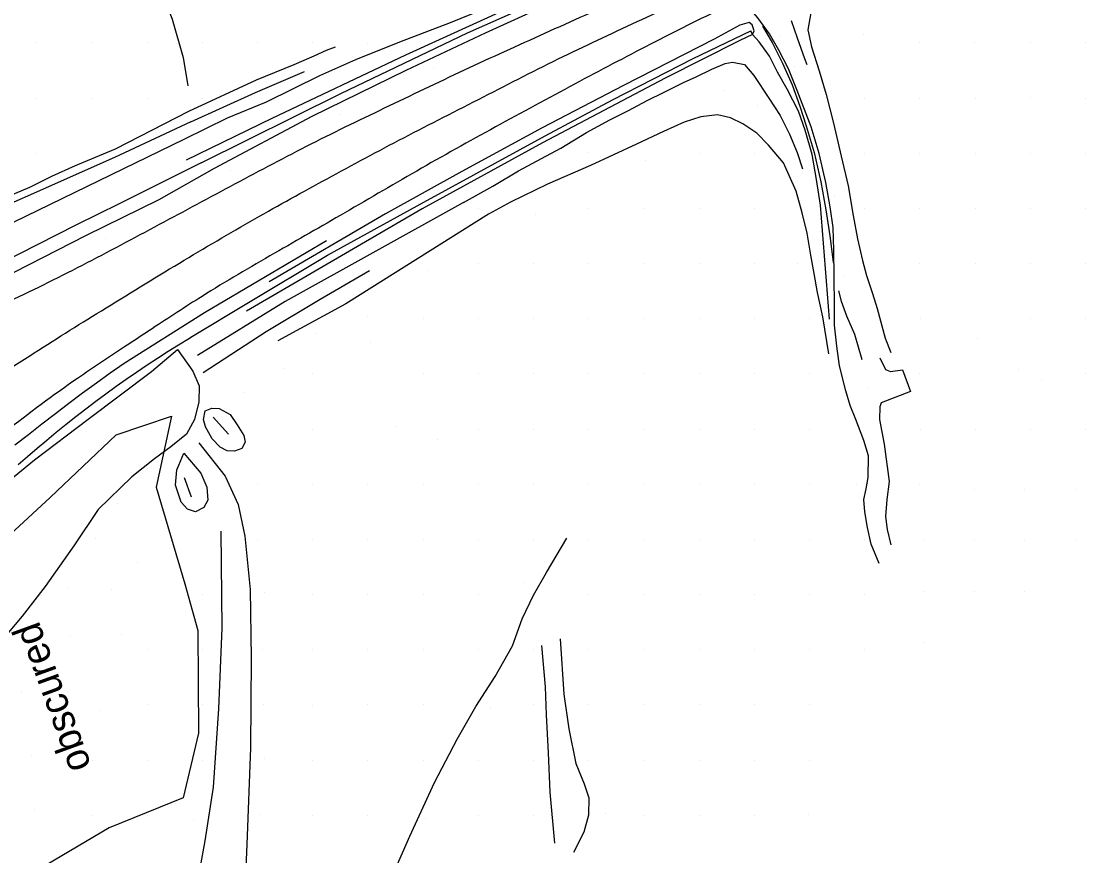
# Model space of a CAD drawing. Extents: x 524772 to 528246, y 273285 to 283088.
# Drawn here: x 527033.7 to 527223, y 277405.3 to 277552.7 of the extents above; entities that cross this region are included whole.
import ezdxf

# ---------------------------------------------------------------- set-up
doc = ezdxf.new("R2010")
doc.units = 0
for name, color, linetype in [('Exist DTM Crownline', 7, 'Continuous'), ('Exist DTM Spot Elevation CELL', 7, 'Continuous'), ('Exist Roads EOP', 7, 'Continuous'), ('Old_Level_12', 7, 'Continuous'), ('PH Exist DTM Breakline', 7, 'Continuous'), ('PH Exist DTM Obscure Area', 7, 'Continuous'), ('PH Exist DTM Point', 7, 'Continuous')]:
    doc.layers.add(name, color=color, linetype=linetype)

msp = doc.modelspace()

# ---------------------------------------------------------------- linework, layer by layer
at = {"layer": 'Exist DTM Crownline'}
msp.add_spline([(527012.9, 277479), (527035.13, 277493.63), (527047.79, 277501.59), (527061.59, 277510.01), (527074.93, 277517.83), (527087.69, 277524.92), (527101.22, 277532.16), (527115.31, 277539.39), (527129.4, 277546.52), (527143.33, 277553.09), (527157.2, 277559.38), (527172, 277565.61), (527185.97, 277571.18), (527200.44, 277576.75), (527213.91, 277581.57), (527228.29, 277586.39), (527242.7, 277590.91), (527257.14, 277595.19), (527271.79, 277599.28)], degree=3, dxfattribs=at)
at = {"layer": 'Exist DTM Spot Elevation CELL'}
msp.add_line((527045.97, 277474.93), (527045.97, 277474.93), dxfattribs=at)
at = {"layer": 'Exist Roads EOP'}
for points in [[(527270.78, 277603.37), (527256.06, 277599.09), (527241.65, 277594.75), (527227.06, 277590.17), (527212.47, 277585.21), (527198.44, 277580.12), (527184.35, 277574.63), (527170.36, 277569.05), (527155.19, 277563.06), (527141.3, 277557.34), (527127, 277550.99), (527112.8, 277544.51), (527098.63, 277537.78), (527084.82, 277531.02), (527071.32, 277523.94), (527058.01, 277516.8), (527044.38, 277509.59), (527030.61, 277502.78), (527016.27, 277496.31), (527001.86, 277490.41), (526987.67, 277485.12)], [(527272.57, 277596.68), (527258.04, 277592.42), (527243.99, 277587.67), (527229.51, 277583.19), (527215.42, 277578.37), (527201.07, 277573.4), (527187.28, 277567.87), (527173.13, 277562.03), (527158.7, 277555.6), (527145.65, 277549.11), (527132.3, 277542.12), (527118.3, 277534.55), (527104.37, 277526.77), (527090.79, 277518.88), (527078.39, 277511.74), (527065.58, 277504.12), (527056.77, 277498.41), (527052.06, 277495.3), (527043.57, 277489.61), (527030.84, 277480.16), (527019.08, 277470.24), (527008.57, 277460.31), (526997.6, 277449.4)]]:
    msp.add_spline(points, degree=3, dxfattribs=at)
at = {"layer": 'Old_Level_12'}
msp.add_lwpolyline([(526985.25, 277411.31), (526998.8, 277426.7), (527015.52, 277447.03), (527028.53, 277459.17), (527038.72, 277468.55), (527050.4, 277479.65), (527060.21, 277482.96), (527057.46, 277470.38), (527062.53, 277453.28), (527064.85, 277445.08), (527064.96, 277426.88), (527062.27, 277415.48), (527049.18, 277410.15), (527037.93, 277403.49), (527029.44, 277395.78), (527025.35, 277392.96), (527024.45, 277389.54), (527021.62, 277387.08), (527013.37, 277383.47), (527005.76, 277383.08), (526993.31, 277388.45), (526984.9, 277407.03)], dxfattribs=at)
at = {"layer": 'PH Exist DTM Breakline'}
for points in [[(527029.64, 277607.72), (527033.91, 277601.98), (527037.04, 277598.47), (527040.59, 277593.93), (527044.34, 277589.32), (527048.32, 277584.35), (527052.04, 277577.84), (527053.61, 277571.61), (527057.13, 277561.42), (527060.31, 277553.12), (527062.23, 277546.37), (527063.09, 277541.35)], [(527067.81, 277526.76), (527085.06, 277535.97), (527101.63, 277544.09), (527115.66, 277550.72), (527133.31, 277558.81), (527133.9, 277559.09), (527134.17, 277559.51), (527133.43, 277561.02), (527131.86, 277560.35), (527120.05, 277555.21), (527101.51, 277546.74), (527077.94, 277535.54), (527062.77, 277528.22)], [(527065.43, 277527.74), (527090.09, 277539.96), (527112.47, 277550.7), (527133.4, 277560.02)], [(527121.35, 277557.37), (527109.43, 277552.48), (527100.46, 277549.04), (527092.7, 277545.92), (527086.35, 277543.09), (527076.94, 277538.45), (527070.01, 277535.63), (527062.35, 277531.86)], [(527178.21, 277491.85), (527177.74, 277495.31), (527177.36, 277499.01), (527177.34, 277502.43), (527177.28, 277507.62), (527177.22, 277512.26), (527177.09, 277516.29), (527176.57, 277519.94), (527175.8, 277524.23), (527174.63, 277529.4), (527173.2, 277534.12), (527170.76, 277540.53), (527169.2, 277544.36), (527167.51, 277547.62), (527165.87, 277550.51), (527163.78, 277553.37), (527162.68, 277554.66), (527157.8, 277554.15), (527156.97, 277554.25)], [(527173.18, 277554.23), (527172.64, 277551.24), (527173.26, 277548.24), (527174.65, 277543.97), (527175.89, 277539.82), (527177.16, 277534.77), (527178.54, 277528.92), (527179.75, 277523.64), (527180.66, 277518.39), (527181.4, 277514.32), (527182.29, 277510.48), (527183.03, 277507.83), (527184.05, 277504.62), (527184.86, 277501.97), (527186.32, 277496.73), (527187.28, 277494.19)], [(527162.83, 277550.39), (527163.17, 277551.07), (527162.81, 277552.11), (527162.26, 277552.55), (527160.59, 277552.04), (527156.08, 277549.59), (527140.08, 277541.4), (527125.7, 277533.89), (527111.49, 277526.19), (527098.02, 277518.73), (527077.46, 277506.69)], [(527169.71, 277552.91), (527170.76, 277549.84), (527172.03, 277546.16), (527172.45, 277545.12)], [(527162.83, 277550.39), (527160.63, 277549.34), (527147.45, 277542.69), (527125.77, 277531.27), (527104.49, 277519.57), (527073.45, 277501.53)], [(527087.77, 277511.38), (527104.8, 277520.78), (527126.19, 277532.48), (527138.12, 277538.86), (527152.38, 277546.19), (527162.55, 277551.04)], [(527176.49, 277500.12), (527174.85, 277520.24), (527174.18, 277524.79), (527173.43, 277529.18), (527172.17, 277533.52), (527170.96, 277536.87), (527169, 277540.77), (527167.3, 277543.78), (527165.86, 277546.59), (527164.03, 277549.11), (527162.83, 277550.39), (527162.55, 277551.04)], [(527164.6, 277551.91), (527166.31, 277549.03), (527168.14, 277545.33), (527169.86, 277541.49), (527171.2, 277537.75), (527172.32, 277534.24), (527173.77, 277529.53), (527174.96, 277524.38), (527175.84, 277519.42), (527176.51, 277514.83), (527177.14, 277510.19), (527177.15, 277510.11)], [(527063.24, 277536.84), (527075.18, 277542.38), (527081.88, 277545.14), (527085.39, 277546.64), (527087.58, 277547.63), (527089.14, 277548.26)], [(527111.78, 277520.69), (527116.96, 277523.62), (527121.5, 277526.31), (527125.57, 277528.5), (527129, 277530.34), (527133.55, 277533.08), (527137.64, 277535.31), (527140.92, 277536.98), (527144.23, 277538.73), (527147.24, 277540.23), (527150.68, 277541.93), (527152.89, 277542.96), (527155.67, 277544.3), (527158, 277545.27), (527159.34, 277545.52), (527161.44, 277545.12), (527163.12, 277543.19), (527165.73, 277539.15), (527167.72, 277536.12), (527169.37, 277532.8), (527170.76, 277529.58), (527171.71, 277526.64)], [(527063.63, 277534.95), (527075.01, 277540.14), (527083.71, 277543.88)], [(527025.7, 277519.5), (527035.15, 277523.43), (527039.04, 277525.37), (527043.24, 277527.24), (527050.32, 277530.19), (527063.24, 277536.84)], [(527176.35, 277493.99), (527175.31, 277500.52), (527174.36, 277504.82), (527173.73, 277508.17), (527173.18, 277511.41), (527172.5, 277515.3), (527171.62, 277518.88), (527170.56, 277522.74), (527168.34, 277527.71), (527165.69, 277530.88), (527163.61, 277532.96), (527161.17, 277534.6), (527158.99, 277535.71), (527156.65, 277536.21), (527153.73, 277535.87), (527150.78, 277534.93), (527147.14, 277533.27), (527142.37, 277531.03), (527134.21, 277527.24), (527126.62, 277523.93), (527120.1, 277520.75), (527116.19, 277518.64), (527091, 277502.82), (527078.95, 277496.25)], [(527063.63, 277534.95), (527050.12, 277528.7), (527017.93, 277514.39), (527007.64, 277509.27), (526958.35, 277490.57), (526947.83, 277487.25), (526930.21, 277481.91), (526921.71, 277479.07), (526911.59, 277476.32), (526905.56, 277474.55), (526894.03, 277470.8), (526881.77, 277466.68), (526874.81, 277464.71)], [(527062.35, 277531.86), (527019.31, 277510.96), (527008.52, 277506.7), (526971.15, 277490.83), (526956.27, 277485.74), (526924.85, 277476.2), (526912.85, 277473.02), (526901.93, 277470.15), (526894.22, 277467.82), (526885.23, 277465), (526878.81, 277463.4), (526872.26, 277462.31), (526866.92, 277461.65), (526860.41, 277460.41)], [(527065.43, 277527.74), (527050.92, 277520.46), (527043.26, 277516.7), (527023.06, 277506.47)], [(527032.37, 277508.41), (527045.18, 277514.92), (527057.98, 277521.25), (527067.81, 277526.76)], [(527111.78, 277520.69), (527080.26, 277503.19), (527064.79, 277493.64)], [(527087.57, 277513.93), (527066, 277501.19), (527051.83, 277492.27), (527049.37, 277490.53), (527046.92, 277488.77), (527044.48, 277486.99), (527042.06, 277485.19), (527039.66, 277483.37), (527037.27, 277481.53), (527034.89, 277479.67), (527032.53, 277477.79)], [(527033.1, 277474.37), (527034.76, 277475.84), (527036.44, 277477.29), (527038.13, 277478.72), (527039.83, 277480.14), (527041.56, 277481.53), (527043.29, 277482.91), (527045.04, 277484.26), (527046.81, 277485.6), (527048.59, 277486.92), (527050.39, 277488.22), (527052.2, 277489.5), (527054.02, 277490.75), (527055.86, 277491.99), (527057.71, 277493.21), (527059.58, 277494.41), (527061.45, 277495.58), (527063.34, 277496.74), (527063.63, 277496.91), (527073.8, 277503.05), (527087.77, 277511.38)], [(527065.77, 277490.65), (527076.94, 277497.89), (527086.45, 277503.64), (527095.15, 277508.67)], [(527178.08, 277505.12), (527178.5, 277503.28), (527179.48, 277500.7), (527180.9, 277497.42), (527182.18, 277492.98)], [(527185.23, 277456.89), (527183.85, 277460.31), (527183.17, 277463.25), (527182.71, 277466.06), (527182.56, 277468.23), (527182.96, 277470.12), (527183.32, 277472.09), (527183.37, 277475.94), (527182.55, 277478.64), (527181.14, 277482.36), (527180.14, 277484.8), (527179.36, 277487.41), (527178.21, 277491.85)], [(527185.33, 277493.28), (527186.34, 277491.21), (527187.27, 277490.82), (527189.37, 277491.13), (527190.77, 277487.32), (527185.62, 277485.3), (527185.33, 277484.61), (527185.31, 277482.37), (527186.13, 277477.99), (527187, 277471.38), (527186.62, 277468.21), (527186.37, 277465.2), (527186.65, 277462.93), (527187.29, 277460.21)], [(527067.35, 277478.94), (527066.17, 277481.07), (527065.84, 277482.38), (527066.12, 277483.89), (527067.31, 277484.38), (527068.64, 277484.28), (527070.57, 277483.25), (527071.77, 277481.44), (527072.96, 277479.51), (527073.19, 277478.33), (527072.62, 277477.2), (527071.32, 277476.73), (527070.04, 277476.83), (527068.77, 277477.44), (527067.35, 277478.94)], [(527067.56, 277482.76), (527070.24, 277479.79)], [(527065, 277478.23), (527069.7, 277472.34), (527071.99, 277467.32), (527073.16, 277461.72), (527074.06, 277452.3), (527074.26, 277440.14), (527074.17, 277424.31), (527073.51, 277407.25), (527072.93, 277393.76), (527072.77, 277383.09), (527074.19, 277377.88), (527076.18, 277374.75), (527077.89, 277373.26), (527082.45, 277372.14), (527089.59, 277370.85), (527105.79, 277369.94), (527118.86, 277369.65), (527129.85, 277368.57), (527134.5, 277367.52), (527136.83, 277366.1), (527140.6, 277362.79), (527143.4, 277358.9), (527146.2, 277353.21)], [(527062.36, 277476.42), (527065.38, 277472.85), (527066.46, 277470.39), (527066.58, 277468.07), (527065.88, 277466.79), (527064.42, 277466.06), (527062.99, 277466.5), (527061.91, 277467.74), (527060.91, 277470.76), (527061.15, 277473.46), (527061.5, 277474.27), (527062.36, 277476.42)], [(527062.45, 277472.12), (527063.68, 277468.67)], [(527068.93, 277462.64), (527069.08, 277445.49), (527068.51, 277431.2), (527067.54, 277417.37), (527066.08, 277407.89), (527064.58, 277399.74), (527064.32, 277392.42), (527064.9, 277386.93), (527066.11, 277380.8), (527068.58, 277375.41), (527069.7, 277374.19)], [(527098.03, 277398.89), (527102.32, 277408.67), (527106.69, 277418.16), (527110.65, 277425.84), (527113.96, 277431.62), (527117.4, 277436.9), (527120.43, 277442.33), (527122.13, 277447.11), (527124.14, 277451.28), (527126.45, 277455.31), (527130.04, 277461.4)], [(527127.93, 277407.46), (527127.08, 277416.47), (527126.82, 277423.4), (527126.48, 277430.12), (527126.28, 277435.1), (527125.64, 277442.41)], [(527128.89, 277443.57), (527129.51, 277433.8), (527130.43, 277427.65), (527131.64, 277421.53), (527133.13, 277417.92), (527133.92, 277415.45), (527133.88, 277412.41), (527133.07, 277409.39), (527131.23, 277405.8)]]:
    msp.add_lwpolyline(points, dxfattribs=at)
at = {"layer": 'PH Exist DTM Obscure Area'}
for points in [[(527022.51, 277464.18), (527035.99, 277475.25), (527045.49, 277482.44), (527056.63, 277490.85), (527061.25, 277494.75)], [(527061.25, 277494.75), (527063.97, 277490.91), (527065.06, 277488.31), (527065.02, 277485.47), (527064.25, 277482.33), (527062.84, 277479.78), (527060.07, 277477.5), (527057.17, 277475.39), (527053.15, 277472.24), (527047.25, 277466.43), (527042.95, 277460.01), (527037.86, 277452.84), (527033.79, 277447.59), (527030.39, 277443.54)]]:
    msp.add_lwpolyline(points, dxfattribs=at)
at = {"layer": 'PH Exist DTM Point'}
for p, q in [((527182.52, 277550.47), (527182.52, 277550.47)), ((527036.39, 277548.93), (527036.39, 277548.93)), ((527046.14, 277548.93), (527046.14, 277548.93)), ((527055.9, 277548.93), (527055.9, 277548.93)), ((527065.63, 277548.92), (527065.63, 277548.92)), ((527075.4, 277548.93), (527075.4, 277548.93)), ((527085.16, 277548.93), (527085.16, 277548.93)), ((527094.91, 277548.9), (527094.91, 277548.9)), ((527167.6, 277550.15), (527167.6, 277550.15)), ((527192.45, 277548.93), (527192.45, 277548.93)), ((527202.17, 277548.98), (527202.17, 277548.98)), ((527211.96, 277548.93), (527211.96, 277548.93)), ((527221.68, 277548.94), (527221.68, 277548.94)), ((527170.32, 277544.82), (527170.32, 277544.82)), ((527106.48, 277544.49), (527106.48, 277544.49)), ((527036.39, 277539.18), (527036.39, 277539.18)), ((527046.14, 277539.18), (527046.14, 277539.18)), ((527055.9, 277539.18), (527055.9, 277539.18)), ((527065.65, 277539.18), (527065.65, 277539.18)), ((527157.93, 277540.49), (527157.93, 277540.49)), ((527182.69, 277539.18), (527182.69, 277539.18)), ((527192.45, 277539.18), (527192.45, 277539.18)), ((527202.2, 277539.18), (527202.2, 277539.18)), ((527211.95, 277539.22), (527211.95, 277539.22)), ((527221.71, 277539.18), (527221.71, 277539.18)), ((527163.67, 277537.89), (527163.67, 277537.89)), ((527089.98, 277536.3), (527089.98, 277536.3)), ((527174.26, 277534.57), (527174.26, 277534.57)), ((527133.84, 277529.64), (527133.84, 277529.64)), ((527036.39, 277529.42), (527036.39, 277529.42)), ((527144.03, 277528.14), (527144.03, 277528.14)), ((527153.43, 277529.42), (527153.43, 277529.42)), ((527163.19, 277529.42), (527163.19, 277529.42)), ((527182.69, 277529.42), (527182.69, 277529.42)), ((527192.45, 277529.42), (527192.45, 277529.42)), ((527202.2, 277529.42), (527202.2, 277529.42)), ((527211.97, 277529.41), (527211.97, 277529.41)), ((527221.71, 277529.42), (527221.71, 277529.42)), ((527070.65, 277526.3), (527070.65, 277526.3)), ((527177.39, 277521.82), (527177.39, 277521.82)), ((527114.42, 277519.67), (527114.42, 277519.67)), ((527124.51, 277518.65), (527124.51, 277518.65)), ((527133.93, 277519.67), (527133.93, 277519.67)), ((527143.68, 277519.64), (527143.68, 277519.64)), ((527153.43, 277519.67), (527153.43, 277519.67)), ((527163.19, 277519.67), (527163.19, 277519.67)), ((527182.69, 277519.67), (527182.69, 277519.67)), ((527192.45, 277519.67), (527192.45, 277519.67)), ((527202.2, 277519.67), (527202.2, 277519.67)), ((527212.01, 277519.59), (527212.01, 277519.59)), ((527221.72, 277519.65), (527221.72, 277519.65)), ((527048.55, 277514.44), (527048.55, 277514.44)), ((527105.45, 277508.76), (527105.45, 277508.76)), ((527114.42, 277509.92), (527114.42, 277509.92)), ((527124.17, 277509.92), (527124.17, 277509.92)), ((527133.93, 277509.92), (527133.93, 277509.92)), ((527143.68, 277509.92), (527143.68, 277509.92)), ((527153.43, 277509.92), (527153.43, 277509.92)), ((527163.19, 277509.92), (527163.19, 277509.92)), ((527170.75, 277509.91), (527170.75, 277509.91)), ((527192.45, 277509.92), (527192.45, 277509.92)), ((527202.2, 277509.92), (527202.2, 277509.92)), ((527211.96, 277509.92), (527211.96, 277509.92)), ((527221.71, 277509.92), (527221.71, 277509.92)), ((527179.1, 277507.7), (527179.1, 277507.7)), ((527094.83, 277500.57), (527094.83, 277500.57)), ((527104.67, 277500.16), (527104.67, 277500.16)), ((527114.42, 277500.16), (527114.42, 277500.16)), ((527124.17, 277500.16), (527124.17, 277500.16)), ((527133.93, 277500.16), (527133.93, 277500.16)), ((527143.68, 277500.19), (527143.68, 277500.19)), ((527153.43, 277500.16), (527153.43, 277500.16)), ((527163.19, 277500.16), (527163.19, 277500.16)), ((527172.94, 277500.16), (527172.94, 277500.16)), ((527192.46, 277500.15), (527192.46, 277500.15)), ((527211.96, 277500.16), (527211.96, 277500.16)), ((527221.71, 277500.16), (527221.71, 277500.16)), ((527085.65, 277497.47), (527085.65, 277497.47)), ((527180.28, 277497.9), (527180.28, 277497.9)), ((527095.3, 277495.93), (527095.3, 277495.93)), ((527202.58, 277496.66), (527202.58, 277496.66)), ((527080, 277491.44), (527080, 277491.44)), ((527085.16, 277490.41), (527085.16, 277490.41)), ((527104.67, 277490.41), (527104.67, 277490.41)), ((527114.42, 277490.41), (527114.42, 277490.41)), ((527124.17, 277490.41), (527124.17, 277490.41)), ((527133.93, 277490.41), (527133.93, 277490.41)), ((527143.68, 277490.41), (527143.68, 277490.41)), ((527153.43, 277490.41), (527153.43, 277490.41)), ((527163.19, 277490.41), (527163.19, 277490.41)), ((527172.94, 277490.41), (527172.94, 277490.41)), ((527192.45, 277490.44), (527192.45, 277490.44)), ((527209.88, 277491.12), (527209.88, 277491.12)), ((527221.68, 277490.41), (527221.68, 277490.41)), ((527183.18, 277488.01), (527183.18, 277488.01)), ((527213.84, 277489.17), (527213.84, 277489.17)), ((527073.1, 277487.09), (527073.1, 277487.09)), ((527085.16, 277480.66), (527085.16, 277480.66)), ((527099.85, 277481.15), (527099.85, 277481.15)), ((527114.42, 277480.66), (527114.42, 277480.66)), ((527124.17, 277480.66), (527124.17, 277480.66)), ((527133.93, 277480.66), (527133.93, 277480.66)), ((527143.68, 277480.66), (527143.68, 277480.66)), ((527153.43, 277480.66), (527153.43, 277480.66)), ((527163.19, 277480.66), (527163.19, 277480.66)), ((527172.94, 277480.66), (527172.94, 277480.66)), ((527192.46, 277480.61), (527192.46, 277480.61)), ((527202.2, 277480.66), (527202.2, 277480.66)), ((527211.96, 277480.66), (527211.96, 277480.66)), ((527221.71, 277480.66), (527221.71, 277480.66)), ((527107.14, 277478.84), (527107.14, 277478.84)), ((527055.92, 277473.66), (527055.92, 277473.66)), ((527075.39, 277470.92), (527075.39, 277470.92)), ((527085.16, 277470.9), (527085.16, 277470.9)), ((527094.91, 277470.9), (527094.91, 277470.9)), ((527104.65, 277470.89), (527104.65, 277470.89)), ((527114.4, 277470.89), (527114.4, 277470.89)), ((527124.17, 277470.9), (527124.17, 277470.9)), ((527133.93, 277470.9), (527133.93, 277470.9)), ((527143.68, 277470.9), (527143.68, 277470.9)), ((527153.43, 277470.9), (527153.43, 277470.9)), ((527163.19, 277470.9), (527163.19, 277470.9)), ((527172.94, 277470.9), (527172.94, 277470.9)), ((527181.27, 277470.82), (527181.27, 277470.82)), ((527192.45, 277470.9), (527192.45, 277470.9)), ((527202, 277470), (527202, 277470)), ((527211, 277470), (527211, 277470)), ((527220, 277470), (527220, 277470)), ((527050.57, 277467.55), (527050.57, 277467.55)), ((527058.45, 277464.55), (527058.45, 277464.55)), ((527046.7, 277461.25), (527046.7, 277461.25)), ((527075.4, 277461.15), (527075.4, 277461.15)), ((527085.16, 277461.15), (527085.16, 277461.15)), ((527094.91, 277461.15), (527094.91, 277461.15)), ((527104.68, 277461.16), (527104.68, 277461.16)), ((527114.43, 277461.16), (527114.43, 277461.16)), ((527124.17, 277461.15), (527124.17, 277461.15)), ((527133.93, 277461.15), (527133.93, 277461.15)), ((527143.68, 277461.15), (527143.68, 277461.15)), ((527153.43, 277461.15), (527153.43, 277461.15)), ((527163.19, 277461.15), (527163.19, 277461.15)), ((527172.94, 277461.15), (527172.94, 277461.15)), ((527182.69, 277461.15), (527182.69, 277461.15)), ((527193, 277461), (527193, 277461)), ((527202, 277461), (527202, 277461)), ((527211, 277461), (527211, 277461)), ((527219.99, 277460.97), (527219.99, 277460.97)), ((527054.12, 277457.09), (527054.12, 277457.09)), ((527061.95, 277454.2), (527061.95, 277454.2)), ((527041.9, 277452.55), (527041.9, 277452.55)), ((527049.59, 277452.26), (527049.59, 277452.26)), ((527122.37, 277453.51), (527122.37, 277453.51)), ((527193, 277452), (527193, 277452)), ((527202, 277452), (527202, 277452)), ((527211, 277452), (527211, 277452)), ((527065.65, 277451.39), (527065.65, 277451.39)), ((527076.61, 277451.72), (527076.61, 277451.72)), ((527085.16, 277451.39), (527085.16, 277451.39)), ((527094.91, 277451.39), (527094.91, 277451.39)), ((527104.67, 277451.39), (527104.67, 277451.39)), ((527114.42, 277451.39), (527114.42, 277451.39)), ((527133.93, 277451.39), (527133.93, 277451.39)), ((527143.68, 277451.39), (527143.68, 277451.39)), ((527153.43, 277451.39), (527153.43, 277451.39)), ((527163.19, 277451.39), (527163.19, 277451.39)), ((527172.94, 277451.39), (527172.94, 277451.39)), ((527182.69, 277451.39), (527182.69, 277451.39)), ((527051.41, 277444.38), (527051.41, 277444.38)), ((527033.72, 277443.73), (527033.72, 277443.73)), ((527042.27, 277443.98), (527042.27, 277443.98)), ((527193, 277443), (527193, 277443)), ((527056.09, 277441.61), (527056.09, 277441.61)), ((527065.65, 277441.64), (527065.65, 277441.64)), ((527076.19, 277441.73), (527076.19, 277441.73)), ((527085.17, 277441.65), (527085.17, 277441.65)), ((527094.91, 277441.64), (527094.91, 277441.64)), ((527104.67, 277441.64), (527104.67, 277441.64)), ((527114.42, 277441.64), (527114.42, 277441.64)), ((527124.17, 277441.64), (527124.17, 277441.64)), ((527133.93, 277441.64), (527133.93, 277441.64)), ((527143.68, 277441.64), (527143.68, 277441.64)), ((527153.43, 277441.64), (527153.43, 277441.64)), ((527163.19, 277441.64), (527163.19, 277441.64)), ((527172.94, 277441.64), (527172.94, 277441.64)), ((527182.69, 277441.64), (527182.69, 277441.64)), ((527033.69, 277434.16), (527033.69, 277434.16)), ((527041.88, 277434.31), (527041.88, 277434.31)), ((527055.9, 277431.89), (527055.9, 277431.89)), ((527065.65, 277431.89), (527065.65, 277431.89)), ((527076.38, 277432.05), (527076.38, 277432.05)), ((527085.14, 277431.88), (527085.14, 277431.88)), ((527094.91, 277431.89), (527094.91, 277431.89)), ((527104.67, 277431.89), (527104.67, 277431.89)), ((527116.56, 277431.19), (527116.56, 277431.19)), ((527124.17, 277431.89), (527124.17, 277431.89)), ((527133.93, 277431.89), (527133.93, 277431.89)), ((527143.68, 277431.89), (527143.68, 277431.89)), ((527153.43, 277431.89), (527153.43, 277431.89)), ((527163.19, 277431.89), (527163.19, 277431.89)), ((527172.94, 277431.89), (527172.94, 277431.89)), ((527047.65, 277430.97), (527047.65, 277430.97)), ((527035.53, 277423.04), (527035.53, 277423.04)), ((527046.16, 277422.12), (527046.16, 277422.12)), ((527055.9, 277422.13), (527055.9, 277422.13)), ((527065.65, 277422.13), (527065.65, 277422.13)), ((527076.59, 277422.42), (527076.59, 277422.42)), ((527085.16, 277422.13), (527085.16, 277422.13)), ((527094.91, 277422.13), (527094.91, 277422.13)), ((527104.67, 277422.13), (527104.67, 277422.13)), ((527114.42, 277422.13), (527114.42, 277422.13)), ((527124.17, 277422.13), (527124.17, 277422.13)), ((527133.93, 277422.13), (527133.93, 277422.13)), ((527143.68, 277422.13), (527143.68, 277422.13)), ((527153.43, 277422.13), (527153.43, 277422.13)), ((527163.19, 277422.13), (527163.19, 277422.13)), ((527172.94, 277422.13), (527172.94, 277422.13)), ((527035.99, 277413.34), (527035.99, 277413.34)), ((527046.14, 277412.38), (527046.14, 277412.38)), ((527055.9, 277412.38), (527055.9, 277412.38)), ((527075.88, 277412.44), (527075.88, 277412.44)), ((527085.16, 277412.38), (527085.16, 277412.38)), ((527094.91, 277412.38), (527094.91, 277412.38)), ((527114.42, 277412.38), (527114.42, 277412.38)), ((527124.17, 277412.38), (527124.17, 277412.38)), ((527136.95, 277412.67), (527136.95, 277412.67)), ((527143.68, 277412.38), (527143.68, 277412.38)), ((527153.43, 277412.38), (527153.43, 277412.38)), ((527163.19, 277412.38), (527163.19, 277412.38)), ((527172.75, 277412.61), (527172.75, 277412.61)), ((527064.1, 277411.52), (527064.1, 277411.52)), ((527105.13, 277411.76), (527105.13, 277411.76))]:
    msp.add_line(p, q, dxfattribs=at)

# ---------------------------------------------------------------- texts
at = {"layer": 'Old_Level_12'}
msp.add_text('obscured', height=5, rotation=110, dxfattribs=at).set_placement((527046.08, 277421.08))

doc.saveas('drawing.dxf')
